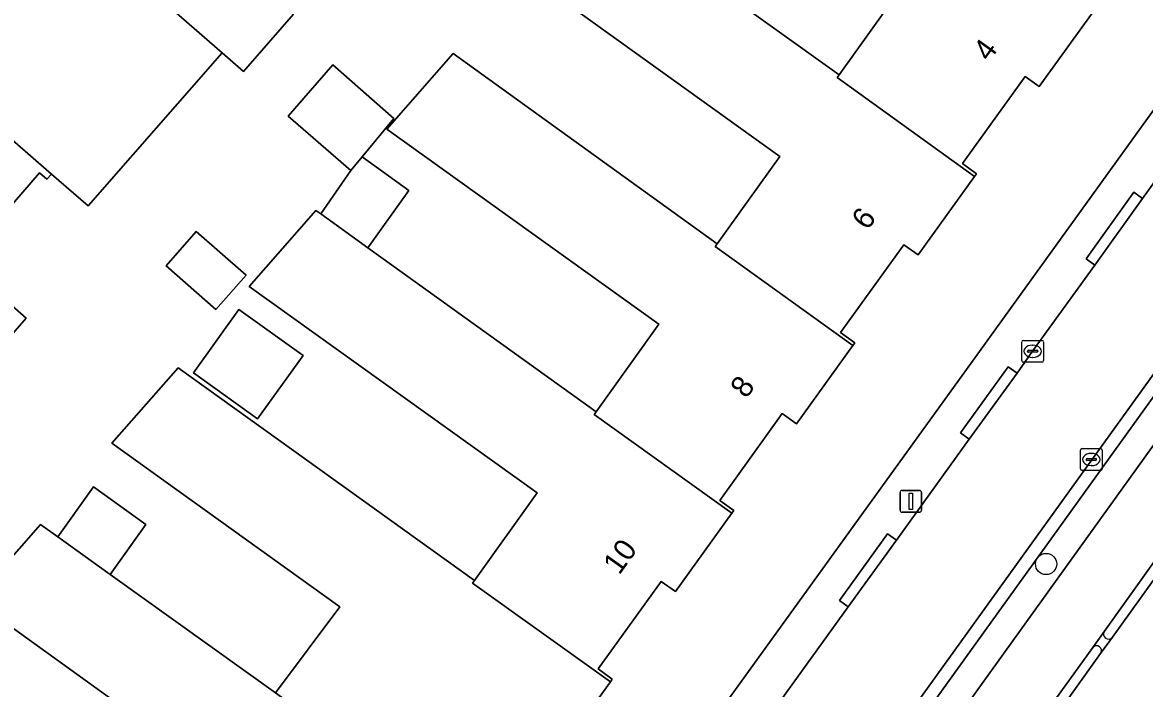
# Model space of a CAD drawing. Extents: x 158835 to 160077, y 386387 to 387778.
# Drawn here: x 159223.8 to 159275.3, y 386843.5 to 386874.1 of the extents above; entities that cross this region are included whole.
import ezdxf

# ---------------------------------------------------------------- set-up
doc = ezdxf.new("R2010")
doc.units = 0
for name, color, linetype in [('IMGEO_Boom', 7, 'Continuous'), ('IMGEO_Erf', 7, 'Continuous'), ('IMGEO_Fietspad_gesloten', 7, 'Continuous'), ('IMGEO_Groenvoorziening', 7, 'Continuous'), ('IMGEO_Haag', 7, 'Continuous'), ('IMGEO_Kolk', 7, 'Continuous'), ('IMGEO_Lichtmast', 7, 'Continuous'), ('IMGEO_OVBaan_gesloten', 7, 'Continuous'), ('IMGEO_Pand', 7, 'Continuous'), ('IMGEO_Pand_nummerreeks', 7, 'Continuous'), ('IMGEO_Rijbaan_lokaal_open', 7, 'Continuous'), ('IMGEO_Verkeerseiland_gesloten', 7, 'Continuous'), ('IMGEO_Voetpad_open', 7, 'Continuous')]:
    doc.layers.add(name, color=color, linetype=linetype)

msp = doc.modelspace()

# ---------------------------------------------------------------- linework, layer by layer
at = {"layer": 'IMGEO_Boom'}
msp.add_circle((159270.803, 386849.208), 0.489, dxfattribs=at)
at = {"layer": 'IMGEO_Erf'}
for points in [[(159250.309, 386879.575), (159252.121, 386882.09), (159254.029, 386880.721), (159252.222, 386878.203), (159261.297, 386871.692), (159264.16, 386875.708), (159253.134, 386883.625), (159256.2, 386887.125), (159263.288, 386882.016), (159266.18, 386886.027), (159259.472, 386890.864), (159265.812, 386898.129), (159263.427, 386900.23), (159267.244, 386904.559), (159267.108, 386904.678), (159267.248, 386904.836), (159267.781, 386905.402), (159267.952, 386905.515), (159262.274, 386914.62), (159257.972, 386921.518)], [(159268.011, 386859.357), (159282.621, 386879.644), (159282.72, 386879.799), (159282.804, 386879.962), (159282.873, 386880.132), (159282.914, 386880.267)], [(159232.697, 386839.52), (159221.551, 386847.538), (159224.603, 386851.031), (159225.399, 386850.46), (159227.04, 386852.752), (159229.451, 386851.021), (159227.807, 386848.731), (159235.399, 386843.28), (159238.363, 386847.237), (159227.886, 386854.768), (159230.926, 386858.231), (159244.539, 386848.455), (159247.422, 386852.473), (159234.187, 386861.964), (159237.26, 386865.463), (159237.48, 386865.305), (159238.864, 386867.292), (159235.979, 386869.801), (159238.033, 386872.151), (159240.843, 386869.694), (159239.39, 386867.931), (159241.533, 386866.382), (159239.645, 386863.746), (159250.125, 386856.202), (159253.015, 386860.236), (159240.517, 386869.19), (159243.562, 386872.673), (159255.686, 386863.926), (159258.576, 386867.946), (159247.61, 386875.829)], [(159273.089, 386874.764), (159270.49, 386871.156), (159269.841, 386871.623), (159266.956, 386867.616), (159267.605, 386867.149), (159267.517, 386867.026), (159264.919, 386863.419), (159264.27, 386863.886), (159261.361, 386859.847), (159262.01, 386859.38), (159261.922, 386859.258), (159259.33, 386855.657), (159258.681, 386856.125), (159255.807, 386852.134), (159256.456, 386851.667), (159256.368, 386851.544), (159253.77, 386847.937), (159253.121, 386848.404), (159250.224, 386844.381), (159250.873, 386843.914), (159250.785, 386843.792), (159248.187, 386840.183)], [(159236.232, 386874.479), (159233.929, 386871.842), (159232.951, 386872.699), (159226.793, 386865.673), (159225.108, 386867.132), (159224.901, 386866.893), (159224.565, 386867.184), (159221.012, 386863.082), (159221.347, 386862.79), (159223.953, 386860.513), (159221.602, 386857.823), (159218.995, 386860.101), (159218.783, 386859.862), (159218.328, 386860.266), (159215.2, 386857.609), (159211.933, 386853.874), (159212.835, 386853.085), (159212.625, 386852.844), (159212.173, 386853.238), (159209.538, 386850.217), (159209.847, 386849.948), (159208.445, 386848.292)], [(159253.399, 386839.081), (159268.011, 386859.357)]]:
    msp.add_lwpolyline(points, dxfattribs=at)
for points in [[(159230.373, 386862.913), (159231.763, 386864.496), (159234.051, 386862.487), (159232.661, 386860.905)], [(159231.631, 386858.001), (159233.723, 386860.914), (159236.667, 386858.8), (159234.575, 386855.887)]]:
    msp.add_lwpolyline(points, close=True, dxfattribs=at)
at = {"layer": 'IMGEO_Fietspad_gesloten'}
for points in [[(159291.313, 386876.256), (159290.843, 386875.635), (159289.915, 386874.409), (159260.77, 386833.848)], [(159242.073, 386795.583), (159244.248, 386800.111), (159244.68, 386800.944), (159246.955, 386805.428), (159247.374, 386806.27), (159249.766, 386810.71), (159250.234, 386811.517), (159252.754, 386815.852), (159253.231, 386816.66), (159255.867, 386820.937), (159256.371, 386821.725), (159259.131, 386825.94), (159259.672, 386826.703), (159262.563, 386830.847), (159263.08, 386831.588), (159265.97, 386835.682), (159266.538, 386836.462), (159269.44, 386840.528), (159270.006, 386841.288), (159272.946, 386845.362), (159273.477, 386846.12), (159276.398, 386850.189)]]:
    msp.add_lwpolyline(points, dxfattribs=at)
at = {"layer": 'IMGEO_Groenvoorziening'}
for points in [[(159260.77, 386833.848), (159289.915, 386874.409)], [(159286.185, 386872.449), (159272.905, 386854.001), (159260.043, 386836.113), (159256.377, 386831.036), (159250.502, 386822.26), (159249.891, 386821.241), (159239.618, 386802.301), (159238.66, 386800.288), (159238.645, 386800.261), (159238.163, 386799.488), (159237.614, 386798.761)], [(159238.109, 386798.417), (159238.681, 386799.182), (159239.189, 386800.003), (159240.155, 386802.033), (159241.476, 386804.683), (159243.604, 386808.803), (159245.802, 386812.886), (159248.07, 386816.93), (159250.404, 386820.929), (159251.714, 386823.086), (159253.364, 386825.663), (159255.079, 386828.194), (159256.863, 386830.685), (159260.53, 386835.762), (159273.392, 386853.651), (159286.673, 386872.099)], [(159286.673, 386872.099), (159273.392, 386853.651), (159260.53, 386835.762), (159256.863, 386830.685), (159255.079, 386828.194), (159253.364, 386825.663), (159251.714, 386823.086), (159250.404, 386820.929), (159248.07, 386816.93), (159245.802, 386812.886), (159243.604, 386808.803), (159241.476, 386804.683), (159240.155, 386802.033), (159239.189, 386800.003), (159238.681, 386799.182), (159238.109, 386798.417)]]:
    msp.add_lwpolyline(points, dxfattribs=at)
at = {"layer": 'IMGEO_Haag'}
for points in [[(159286.185, 386872.449), (159272.905, 386854.001), (159260.043, 386836.113), (159256.377, 386831.036), (159250.502, 386822.26), (159249.891, 386821.241), (159239.618, 386802.301), (159238.66, 386800.288), (159238.645, 386800.261), (159238.163, 386799.488), (159237.614, 386798.761)], [(159238.109, 386798.417), (159238.681, 386799.182), (159239.189, 386800.003), (159240.155, 386802.033), (159241.476, 386804.683), (159243.604, 386808.803), (159245.802, 386812.886), (159248.07, 386816.93), (159250.404, 386820.929), (159251.714, 386823.086), (159253.364, 386825.663), (159255.079, 386828.194), (159256.863, 386830.685), (159260.53, 386835.762), (159273.392, 386853.651), (159286.673, 386872.099)]]:
    msp.add_lwpolyline(points, dxfattribs=at)
at = {"layer": 'IMGEO_Kolk'}
for p, q in [((159269.685, 386858.561), (159269.685, 386859.413)), ((159269.76, 386859.487), (159270.612, 386859.487)), ((159270.173, 386859.267), (159270.198, 386859.267)), ((159270.686, 386859.413), (159270.686, 386858.561)), ((159269.944, 386858.981), (159269.944, 386858.993)), ((159270.382, 386858.944), (159269.984, 386858.944)), ((159269.987, 386859.03), (159270.385, 386859.03)), ((159270.428, 386858.993), (159270.428, 386858.981)), ((159270.612, 386858.487), (159269.76, 386858.487)), ((159270.196, 386858.707), (159270.171, 386858.707)), ((159272.379, 386853.587), (159272.379, 386854.439)), ((159272.454, 386854.513), (159273.306, 386854.513)), ((159272.867, 386854.293), (159272.892, 386854.293)), ((159273.38, 386854.439), (159273.38, 386853.587)), ((159272.638, 386854.007), (159272.638, 386854.019)), ((159273.076, 386853.97), (159272.678, 386853.97)), ((159272.681, 386854.056), (159273.079, 386854.056)), ((159272.89, 386853.733), (159272.865, 386853.733)), ((159273.122, 386854.019), (159273.122, 386854.007)), ((159273.306, 386853.513), (159272.454, 386853.513))]:
    msp.add_line(p, q, dxfattribs=at)
for points in [[(159269.685, 386858.561), (159269.685, 386859.413)], [(159269.76, 386859.487), (159270.612, 386859.487)], [(159270.686, 386859.413), (159270.686, 386858.561)], [(159270.612, 386858.487), (159269.76, 386858.487)], [(159272.379, 386853.587), (159272.379, 386854.439)], [(159272.454, 386854.513), (159273.306, 386854.513)], [(159273.38, 386854.439), (159273.38, 386853.587)], [(159273.306, 386853.513), (159272.454, 386853.513)]]:
    msp.add_lwpolyline(points, dxfattribs=at)
for centre, radius, start, end in [((159269.762, 386859.411), 0.0765, 91.552, 178.448), ((159269.762, 386859.411), 0.0765, 91.552, 178.448), ((159270.61, 386859.411), 0.0765, 1.552, 88.448), ((159270.61, 386859.411), 0.0765, 1.552, 88.448), ((159269.984, 386858.99), 0.0403, 85.8775, 175.7526), ((159269.981, 386858.98), 0.0366, 178.938, 274.7102), ((159270.385, 386858.987), 0.043, 264.8664, 352.4533), ((159270.389, 386858.992), 0.0386, 1.7309, 96.639), ((159269.762, 386858.563), 0.0765, 181.552, 268.448), ((159269.762, 386858.563), 0.0765, 181.552, 268.448), ((159270.61, 386858.563), 0.0765, 271.552, 358.448), ((159270.61, 386858.563), 0.0765, 271.552, 358.448), ((159272.456, 386854.437), 0.0765, 91.552, 178.448), ((159272.456, 386854.437), 0.0765, 91.552, 178.448), ((159273.304, 386854.437), 0.0765, 1.552, 88.448), ((159273.304, 386854.437), 0.0765, 1.552, 88.448), ((159272.456, 386853.589), 0.0765, 181.552, 268.448), ((159272.456, 386853.589), 0.0765, 181.552, 268.448), ((159272.678, 386854.016), 0.0403, 85.8775, 175.7526), ((159272.675, 386854.006), 0.0366, 178.938, 274.7102), ((159273.079, 386854.013), 0.043, 264.8664, 352.4533), ((159273.083, 386854.018), 0.0386, 1.7309, 96.639), ((159273.304, 386853.589), 0.0765, 271.552, 358.448), ((159273.304, 386853.589), 0.0765, 271.552, 358.448)]:
    msp.add_arc(centre, radius, start, end, dxfattribs=at)
for centre, major_axis, ratio, start_param, end_param in [((159270.172, 386858.987), (-0.387, 0.002), 0.722429, 4.712389, 7.853982), ((159270.197, 386858.987), (-0.39, 0.002), 0.717154, 1.570796, 4.712389), ((159272.866, 386854.013), (-0.387, 0.002), 0.722429, 4.712389, 7.853982), ((159272.891, 386854.013), (-0.39, 0.002), 0.717154, 1.570796, 4.712389)]:
    msp.add_ellipse(centre, major_axis=major_axis, ratio=ratio, start_param=start_param, end_param=end_param, dxfattribs=at)
at = {"layer": 'IMGEO_Lichtmast'}
for p, q in [((159264.19, 386852.588), (159264.98, 386852.588)), ((159264.98, 386852.588), (159264.19, 386852.588)), ((159264.09, 386851.688), (159264.09, 386852.488)), ((159264.09, 386852.488), (159264.09, 386851.688)), ((159265.08, 386852.488), (159265.08, 386851.688)), ((159265.08, 386851.688), (159265.08, 386852.488)), ((159264.98, 386851.588), (159264.19, 386851.588)), ((159264.19, 386851.588), (159264.98, 386851.588))]:
    msp.add_line(p, q, dxfattribs=at)
msp.add_lwpolyline([(159264.51, 386852.463), (159264.66, 386852.463), (159264.66, 386851.713), (159264.51, 386851.713), (159264.51, 386852.463)], dxfattribs=at)
for centre, start, end in [((159264.19, 386852.488), 90, 180), ((159264.19, 386852.488), 90, 180), ((159264.98, 386852.488), 0, 90), ((159264.98, 386852.488), 360, 90), ((159264.19, 386851.688), 180, 270), ((159264.19, 386851.688), 180, 270), ((159264.98, 386851.688), 270, 0), ((159264.98, 386851.688), 270, 0)]:
    msp.add_arc(centre, 0.1, start, end, dxfattribs=at)
at = {"layer": 'IMGEO_OVBaan_gesloten'}
msp.add_lwpolyline([(159276.783, 386849.924), (159273.85, 386845.844), (159273.308, 386845.095), (159270.387, 386841.02), (159269.839, 386840.252), (159266.905, 386836.191), (159266.365, 386835.415), (159263.456, 386831.331), (159262.923, 386830.576), (159260.033, 386826.444), (159259.51, 386825.68), (159256.76, 386821.485), (159256.246, 386820.694), (159253.627, 386816.43), (159253.143, 386815.617), (159250.623, 386811.274), (159250.159, 386810.469), (159247.79, 386806.047), (159247.36, 386805.224), (159245.086, 386800.74), (159244.661, 386799.903), (159242.481, 386795.398)], dxfattribs=at)
at = {"layer": 'IMGEO_Pand'}
for points in [[(159232.951, 386872.699), (159233.929, 386871.842), (159236.232, 386874.479), (159232.666, 386877.603), (159233.624, 386878.694), (159236.742, 386881.364), (159237.199, 386880.955), (159237.414, 386881.195), (159236.505, 386881.984), (159231.368, 386886.458), (159228.552, 386888.918), (159224.573, 386884.363), (159227.39, 386881.903), (159225.234, 386879.434)], [(159261.297, 386871.692), (159261.21, 386871.57), (159267.517, 386867.026), (159267.605, 386867.149), (159266.956, 386867.616), (159269.841, 386871.623), (159270.49, 386871.156), (159273.089, 386874.764), (159266.769, 386879.321), (159263.288, 386882.016), (159256.2, 386887.125), (159253.134, 386883.625), (159264.16, 386875.708)], [(159232.951, 386872.699), (159225.234, 386879.434), (159222.417, 386881.894), (159218.438, 386877.339), (159221.255, 386874.879), (159219.079, 386872.387), (159225.108, 386867.132), (159226.793, 386865.673)], [(159261.21, 386871.57), (159261.297, 386871.692), (159252.222, 386878.203), (159250.309, 386879.575), (159247.61, 386875.829), (159258.576, 386867.946), (159255.686, 386863.926), (159255.598, 386863.804), (159261.922, 386859.258), (159262.01, 386859.38), (159261.361, 386859.847), (159264.27, 386863.886), (159264.919, 386863.419), (159267.517, 386867.026)], [(159219.079, 386872.387), (159216.262, 386874.847), (159212.296, 386870.307), (159215.113, 386867.846), (159212.937, 386865.354), (159218.085, 386860.896), (159218.995, 386860.101), (159221.602, 386857.823), (159223.953, 386860.513), (159221.347, 386862.79), (159221.012, 386863.082), (159224.565, 386867.184), (159224.901, 386866.893), (159225.108, 386867.132)], [(159255.598, 386863.804), (159255.686, 386863.926), (159243.562, 386872.673), (159240.517, 386869.19), (159253.015, 386860.236), (159250.125, 386856.202), (159250.038, 386856.08), (159256.368, 386851.544), (159256.456, 386851.667), (159255.807, 386852.134), (159258.681, 386856.125), (159259.33, 386855.657), (159261.922, 386859.258)], [(159238.864, 386867.292), (159239.39, 386867.931), (159240.843, 386869.694), (159238.033, 386872.151), (159235.979, 386869.801)], [(159239.39, 386867.931), (159238.864, 386867.292), (159237.48, 386865.305), (159239.645, 386863.746), (159241.533, 386866.382)], [(159250.038, 386856.08), (159250.125, 386856.202), (159239.645, 386863.746), (159237.48, 386865.305), (159237.26, 386865.463), (159234.187, 386861.964), (159247.422, 386852.473), (159244.539, 386848.455), (159244.452, 386848.333), (159250.785, 386843.792), (159250.873, 386843.914), (159250.224, 386844.381), (159253.121, 386848.404), (159253.77, 386847.937), (159256.368, 386851.544)], [(159230.373, 386862.913), (159232.661, 386860.905), (159234.051, 386862.487), (159231.763, 386864.496)], [(159231.631, 386858.001), (159234.575, 386855.887), (159236.667, 386858.8), (159233.723, 386860.914)], [(159245.208, 386836.047), (159245.296, 386836.169), (159244.647, 386836.636), (159247.538, 386840.651), (159248.187, 386840.183), (159250.785, 386843.792), (159244.452, 386848.333), (159244.539, 386848.455), (159230.926, 386858.231), (159227.886, 386854.768), (159238.363, 386847.237), (159235.399, 386843.28), (159238.973, 386840.714), (159238.885, 386840.592)], [(159225.399, 386850.46), (159227.807, 386848.731), (159229.451, 386851.021), (159227.04, 386852.752)], [(159238.885, 386840.592), (159238.973, 386840.714), (159235.399, 386843.28), (159227.807, 386848.731), (159225.399, 386850.46), (159224.603, 386851.031), (159221.551, 386847.538), (159232.697, 386839.52), (159229.812, 386835.509), (159233.382, 386832.944), (159233.294, 386832.822), (159239.613, 386828.276), (159239.701, 386828.399), (159239.052, 386828.867), (159241.96, 386832.905), (159242.609, 386832.438), (159245.208, 386836.047)]]:
    msp.add_lwpolyline(points, close=True, dxfattribs=at)
at = {"layer": 'IMGEO_Rijbaan_lokaal_open'}
for points in [[(159237.614, 386798.761), (159238.163, 386799.488), (159238.645, 386800.261), (159238.66, 386800.288), (159239.618, 386802.301), (159249.891, 386821.241), (159250.502, 386822.26), (159256.377, 386831.036), (159260.043, 386836.113), (159272.905, 386854.001), (159286.185, 386872.449)], [(159278.555, 386870.621), (159275.231, 386866.006), (159273.043, 386862.945), (159270.183, 386858.987), (159269.468, 386857.987), (159267.27, 386854.94), (159263.922, 386850.301), (159261.71, 386847.24), (159258.389, 386842.63)]]:
    msp.add_lwpolyline(points, dxfattribs=at)
at = {"layer": 'IMGEO_Verkeerseiland_gesloten'}
for points in [[(159276.398, 386850.189), (159273.477, 386846.12)], [(159273.85, 386845.844), (159276.783, 386849.924)], [(159272.946, 386845.362), (159270.006, 386841.288)], [(159270.387, 386841.02), (159273.308, 386845.095)]]:
    msp.add_lwpolyline(points, dxfattribs=at)
for centre, radius, start, end in [((159273.67, 386845.99), 0.232, 146.0508, 320.9503), ((159273.122, 386845.222), 0.225, 325.6375, 141.5398)]:
    msp.add_arc(centre, radius, start, end, dxfattribs=at)
at = {"layer": 'IMGEO_Voetpad_open'}
for points in [[(159282.621, 386879.644), (159268.011, 386859.357), (159253.399, 386839.081)], [(159258.389, 386842.63), (159261.71, 386847.24), (159261.305, 386847.532), (159263.517, 386850.593), (159263.922, 386850.301), (159267.27, 386854.94), (159266.864, 386855.233), (159269.063, 386858.279), (159269.468, 386857.987), (159270.183, 386858.987), (159273.043, 386862.945), (159272.637, 386863.235), (159274.825, 386866.296), (159275.231, 386866.006), (159278.555, 386870.621)], [(159273.477, 386846.12), (159272.946, 386845.362)], [(159273.308, 386845.095), (159273.85, 386845.844)]]:
    msp.add_lwpolyline(points, dxfattribs=at)
for points in [[(159273.043, 386862.945), (159275.231, 386866.006), (159274.825, 386866.296), (159272.637, 386863.235)], [(159267.27, 386854.94), (159269.468, 386857.987), (159269.063, 386858.279), (159266.864, 386855.233)], [(159261.71, 386847.24), (159263.922, 386850.301), (159263.517, 386850.593), (159261.305, 386847.532)]]:
    msp.add_lwpolyline(points, close=True, dxfattribs=at)
for centre, radius, start, end in [((159273.67, 386845.99), 0.232, 146.0508, 320.9503), ((159273.122, 386845.222), 0.225, 325.6375, 141.5398)]:
    msp.add_arc(centre, radius, start, end, dxfattribs=at)

# ---------------------------------------------------------------- texts
at = {"layer": 'IMGEO_Pand_nummerreeks'}
for s, rotation, p in [('4', 54.2395, (159268.186, 386872.266)), ('6', 54.2419, (159262.602, 386864.513)), ('8', 54.243, (159257.03, 386856.776)), ('10', 54.2419, (159251.192, 386848.669))]:
    msp.add_text(s, height=1, rotation=rotation, dxfattribs=at).set_placement(p)

doc.saveas('drawing.dxf')
